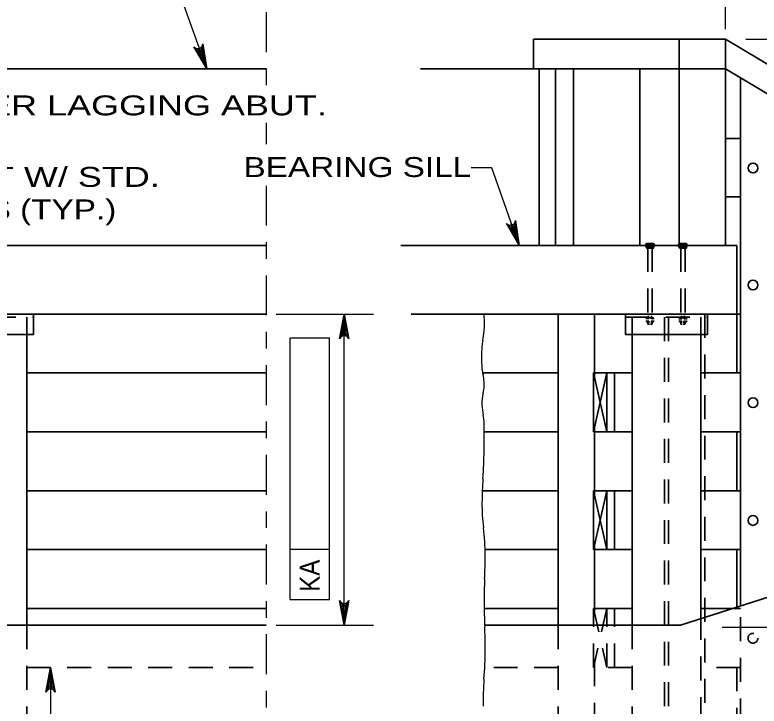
# Model space of a CAD drawing. Extents: x -6.4 to 73.1, y -66 to 0.
# Drawn here: x 46.524 to 51.006, y -62.719 to -58.56 of the extents above; entities that cross this region are included whole.
import ezdxf
from ezdxf.enums import TextEntityAlignment as Align

# ---------------------------------------------------------------- set-up
doc = ezdxf.new("R2010")
doc.units = 0
doc.header["$LTSCALE"] = 0.048
doc.header["$PDMODE"] = 32
doc.header["$PDSIZE"] = 0.024
doc.linetypes.add('DOT_DASHED', pattern=[7.7, 5, -1.2, 0.3, -1.2])
doc.linetypes.add('MEDIUM_DASHED', pattern=[4.5, 3, -1.5])
for name, color, linetype, lineweight in [('3', 7, 'Continuous', 35), ('4', 7, 'Continuous', 25), ('5', 7, 'Continuous', 25), ('8', 7, 'Continuous', 25)]:
    doc.layers.add(name, color=color, linetype=linetype, lineweight=lineweight)

msp = doc.modelspace()

# ---------------------------------------------------------------- hatches: boundary and pattern name
at = {"layer": '4'}
for points in [[(47.65875, -58.77033), (47.62308, -58.78283), (47.6785, -58.88358)], [(49.56125, -59.9465), (49.53158, -59.83175), (49.513, -59.83825)], [(48.48683, -60.478), (48.52625, -60.478), (48.50658, -60.35992)], [(48.48683, -62.1145), (48.52625, -62.1145), (48.50658, -62.23267)], [(46.71958, -62.604), (46.75892, -62.604), (46.73925, -62.48592)]]:
    msp.add_hatch(color=256, dxfattribs=at).paths.add_polyline_path(points)

# ---------------------------------------------------------------- linework, layer by layer
at = {"layer": '3'}
for p, q in [((49.64783, -58.70642), (50.80342, -58.70642)), ((49.64783, -58.70642), (49.64783, -58.88358)), ((50.52408, -58.70642), (50.52408, -58.88358)), ((50.80342, -58.70642), (54.32033, -60.80333)), ((50.80342, -58.70642), (50.80342, -58.88358)), ((42.61283, -58.88358), (48.03658, -58.88358)), ((48.96758, -58.88358), (50.80342, -58.88358)), ((49.68067, -58.88358), (49.68067, -59.9465)), ((49.77892, -58.88358), (49.77892, -59.9465)), ((49.889, -58.88358), (49.889, -59.9465)), ((50.28717, -58.88358), (50.28717, -59.9465)), ((50.52408, -58.88358), (50.52408, -59.9465)), ((50.80342, -58.88358), (54.32033, -60.9805)), ((50.80342, -58.88358), (50.80342, -59.9465)), ((50.89308, -62.1165), (50.89308, -58.93708)), ((50.89308, -59.30242), (50.80342, -59.30242)), ((50.89308, -59.654), (50.80342, -59.654)), ((41.76775, -59.9465), (48.03658, -59.9465)), ((48.84883, -59.9465), (50.87233, -59.9465)), ((50.32783, -59.96242), (50.32783, -59.95025)), ((50.36558, -59.9465), (50.33317, -59.9465)), ((50.33892, -59.95025), (50.33892, -59.96242)), ((50.36025, -59.95025), (50.36025, -59.96242)), ((50.52567, -59.96242), (50.52567, -59.95025)), ((50.56833, -59.96242), (50.52567, -59.96242)), ((50.53067, -59.9465), (50.563, -59.9465)), ((50.536, -59.95025), (50.536, -59.96242)), ((50.55733, -59.95025), (50.55733, -59.96242)), ((50.56833, -59.96242), (50.56833, -59.95025)), ((50.87233, -59.9465), (50.87233, -60.71425)), ((41.76775, -60.35992), (48.03658, -60.35992)), ((46.63633, -60.35992), (46.63633, -60.48292)), ((48.91108, -60.35992), (50.89308, -60.35992)), ((49.7955, -60.35992), (49.7955, -62.23267)), ((50.01558, -60.35992), (50.01558, -60.74467)), ((50.2005, -60.35992), (50.2005, -60.48292)), ((50.69567, -60.35992), (50.69567, -60.48292)), ((50.32742, -60.39133), (50.32742, -60.386)), ((50.32742, -60.40433), (50.32742, -60.39808)), ((50.36517, -60.38225), (50.33275, -60.38225)), ((50.34383, -60.40808), (50.33275, -60.40808)), ((50.34492, -60.375), (50.336, -60.375)), ((50.336, -60.40808), (50.336, -60.42092)), ((50.3385, -60.386), (50.3385, -60.39133)), ((50.3385, -60.39808), (50.3385, -60.40433)), ((50.36225, -60.375), (50.35392, -60.375)), ((50.36517, -60.40808), (50.35433, -60.40808)), ((50.35983, -60.386), (50.35983, -60.39133)), ((50.35983, -60.39808), (50.35983, -60.40433)), ((50.36225, -60.40808), (50.36225, -60.42092)), ((50.37008, -60.39133), (50.37008, -60.386)), ((50.37008, -60.40433), (50.37008, -60.39808)), ((50.526, -60.39192), (50.526, -60.386)), ((50.526, -60.40433), (50.526, -60.398)), ((50.531, -60.38225), (50.56333, -60.38225)), ((50.531, -60.40808), (50.54333, -60.40808)), ((50.53383, -60.375), (50.54333, -60.375)), ((50.53383, -60.40808), (50.53383, -60.42092)), ((50.53633, -60.386), (50.53633, -60.39192)), ((50.53633, -60.398), (50.53633, -60.40433)), ((50.54933, -60.40808), (50.56333, -60.40808)), ((50.5505, -60.375), (50.56008, -60.375)), ((50.55767, -60.386), (50.55767, -60.39192)), ((50.55767, -60.398), (50.55767, -60.40433)), ((50.56008, -60.40808), (50.56008, -60.42092)), ((50.56867, -60.39192), (50.56867, -60.386)), ((50.56867, -60.40433), (50.56867, -60.398)), ((50.3455, -60.42092), (50.336, -60.42092)), ((50.36225, -60.42092), (50.35275, -60.42092)), ((50.53383, -60.42092), (50.54333, -60.42092)), ((50.54933, -60.42092), (50.56008, -60.42092)), ((46.14117, -60.48292), (46.63633, -60.48292)), ((46.59533, -60.48292), (46.59533, -62.23267)), ((50.2005, -60.48292), (50.69567, -60.48292)), ((50.2415, -60.48292), (50.2415, -62.23267)), ((50.65467, -60.48292), (50.65467, -62.1765)), ((46.59533, -60.71425), (48.03658, -60.71425)), ((49.7955, -60.71425), (49.34075, -60.71425)), ((50.00875, -61.06858), (50.00875, -60.71425)), ((50.00875, -60.71425), (50.089, -61.06858)), ((50.089, -60.71425), (50.00875, -61.06858)), ((50.2415, -60.71425), (50.00875, -60.71425)), ((50.089, -61.06858), (50.089, -60.71425)), ((50.13442, -61.06858), (50.13442, -60.71425)), ((50.2415, -60.71425), (50.19825, -60.71425)), ((50.89308, -60.71425), (50.65467, -60.71425)), ((50.01558, -61.03817), (50.01558, -61.45333)), ((46.59533, -61.06858), (48.03658, -61.06858)), ((49.7955, -61.06858), (49.35083, -61.06858)), ((50.2415, -61.06858), (50.00875, -61.06858)), ((54.16433, -61.06375), (50.53233, -62.23267)), ((50.89308, -61.06858), (50.65467, -61.06858)), ((50.87233, -61.06858), (50.87233, -61.42292)), ((46.59533, -61.42292), (48.03658, -61.42292)), ((49.7955, -61.42292), (49.33875, -61.42292)), ((50.00875, -61.77725), (50.00875, -61.42292)), ((50.00875, -61.42292), (50.089, -61.77725)), ((50.2415, -61.42292), (50.00875, -61.42292)), ((50.13442, -61.77725), (50.13442, -61.42292)), ((50.89308, -61.42292), (50.65467, -61.42292)), ((50.01558, -61.74683), (50.01558, -62.162)), ((46.59533, -61.77725), (48.03658, -61.77725)), ((49.7955, -61.77725), (49.356, -61.77725)), ((50.2415, -61.77725), (50.00875, -61.77725)), ((50.89308, -61.77725), (50.65467, -61.77725)), ((50.87233, -61.77725), (50.87233, -62.13158)), ((46.59533, -62.13158), (48.03658, -62.13158)), ((49.7955, -62.13158), (49.35033, -62.13158)), ((50.2415, -62.13158), (50.00875, -62.13158)), ((50.89308, -62.13158), (50.65467, -62.13158)), ((42.0525, -62.23267), (48.03658, -62.23267)), ((49.35308, -62.23267), (50.53233, -62.23267))]:
    msp.add_line(p, q, dxfattribs=at)
at = {"layer": '3', "linetype": 'MEDIUM_DASHED'}
for p, q in [((50.33608, -59.96242), (50.33608, -60.38225)), ((50.36233, -59.96242), (50.36233, -60.38225)), ((50.53392, -59.96242), (50.53392, -60.38225)), ((50.56017, -59.96242), (50.56017, -60.38225)), ((50.67908, -60.35992), (50.67908, -63.54892)), ((50.89308, -63.54892), (50.89308, -62.1165)), ((50.00875, -62.48592), (50.00875, -62.13158)), ((50.00875, -62.13158), (50.089, -62.48592)), ((50.13442, -62.48592), (50.13442, -62.13158)), ((50.65467, -62.1765), (50.65467, -64.00717)), ((46.59533, -62.23267), (46.59533, -64.01633)), ((49.7955, -62.23267), (49.7955, -63.54892)), ((50.2415, -62.23267), (50.2415, -64.01808)), ((50.01558, -62.4555), (50.01558, -62.87067)), ((46.59533, -62.48592), (48.03658, -62.48592)), ((49.7955, -62.48592), (49.35383, -62.48592)), ((50.2415, -62.48592), (50.00875, -62.48592)), ((50.89308, -62.48592), (50.65467, -62.48592)), ((50.87233, -62.48592), (50.87233, -62.84025))]:
    msp.add_line(p, q, dxfattribs=at)
at = {"layer": '3'}
for points in [[(50.32783, -59.96242), (50.3705, -59.96242), (50.3705, -59.95025)], [(50.089, -61.77725), (50.089, -61.42292), (50.00875, -61.77725)]]:
    msp.add_lwpolyline(points, dxfattribs=at)
at = {"layer": '3', "linetype": 'MEDIUM_DASHED'}
msp.add_lwpolyline([(50.089, -62.48592), (50.089, -62.13158), (50.00875, -62.48592)], dxfattribs=at)
at = {"layer": '3'}
for centre in [(50.96877, -59.48111), (50.96877, -60.18474), (50.96877, -60.8934), (50.96877, -61.60206)]:
    msp.add_circle(centre, 0.02953, dxfattribs=at)
at = {"layer": '3', "linetype": 'MEDIUM_DASHED'}
msp.add_circle((50.96877, -62.31072), 0.02953, dxfattribs=at)
at = {"layer": '3'}
for centre, radius, start, end in [((50.33336, -59.95243), 0.00592, 88.17294, 158.71305), ((50.33336, -59.95243), 0.00592, 21.28694, 88.17294), ((50.34954, -59.96347), 0.01696, 51.05, 128.95), ((50.36535, -59.95189), 0.00539, 17.45181, 162.54819), ((50.53082, -59.95189), 0.00539, 17.45181, 162.54819), ((50.54663, -59.96347), 0.01696, 51.05, 128.95), ((50.56281, -59.95243), 0.00592, 91.82706, 158.71306), ((50.56281, -59.95243), 0.00592, 21.28694, 91.82706), ((50.33299, -60.38818), 0.00592, 88.17294, 158.71305), ((50.33299, -60.40216), 0.00592, 201.28694, 271.82706), ((50.33299, -60.38818), 0.00592, 21.28694, 88.17294), ((50.33299, -60.40216), 0.00592, 271.82706, 338.71306), ((50.34917, -60.39922), 0.01696, 51.05, 128.95), ((50.34917, -60.39113), 0.01696, 231.05, 256.0077), ((50.34917, -60.39113), 0.01696, 284.34274, 308.95), ((50.36497, -60.38764), 0.00539, 17.45181, 162.54819), ((50.36497, -60.4027), 0.00539, 197.45181, 342.54819), ((50.5312, -60.38764), 0.00539, 17.45181, 162.54819), ((50.5312, -60.4027), 0.00539, 197.45181, 342.54819), ((50.54701, -60.39922), 0.01696, 51.05, 128.95), ((50.54701, -60.39113), 0.01696, 231.05, 257.49177), ((50.54701, -60.39113), 0.01696, 277.88621, 308.95), ((50.56319, -60.38818), 0.00592, 91.82706, 158.71306), ((50.56319, -60.40216), 0.00592, 201.28694, 268.17294), ((50.56319, -60.38818), 0.00592, 21.28694, 91.82706), ((50.56319, -60.40216), 0.00592, 268.17294, 338.71305)]:
    msp.add_arc(centre, radius, start, end, dxfattribs=at)
at = {"layer": '3', "lineweight": 25}
for centre, radius, start, end in [((48.49638, -60.42412), 0.85604, 0, 4.30041), ((48.04115, -60.29643), 1.31933, 350.22511, 352.77729), ((49.04869, -60.42412), 0.30373, 352.77729, 0), ((50.04974, -60.6168), 0.71552, 174.85038, 180), ((49.73735, -60.58865), 0.40185, 170.22511, 174.85038), ((50.21307, -60.6168), 0.87884, 180, 184.64624), ((49.56984, -60.66908), 0.2335, 184.64624, 194.09577), ((49.09873, -60.78738), 0.25224, 5.00495, 14.09577), ((49.14996, -60.78289), 0.20082, 345.34471, 5.00496), ((49.56975, -60.89267), 0.23309, 165.34471, 183.58075), ((49.83395, -60.87614), 0.4978, 183.58075, 190.71943), ((49.04664, -61.02518), 0.30349, 1.57285, 10.71943), ((47.11271, -61.07828), 2.23815, 0, 1.57285), ((42.6605, -61.07828), 6.69035, 359.0903, 0), ((46.35757, -61.13699), 2.99281, 355.92772, 359.0903), ((51.63092, -61.51242), 2.29388, 175.92772, 179.54026), ((50.48062, -61.50319), 1.14355, 179.54026, 187.19626), ((48.03942, -61.81143), 1.31704, 0.06302, 7.19626), ((46.38007, -61.81325), 2.97639, 357.26093, 0.06302), ((52.03522, -62.0838), 2.68522, 177.26093, 180.21106), ((53.06831, -62.08), 3.71833, 180.21106, 182.50023), ((46.27447, -62.37665), 3.08199, 359.98578, 2.50023), ((47.0813, -62.37685), 2.27516, 355.43722, 359.98579), ((51.16176, -62.70249), 1.81827, 175.43722, 180.5256)]:
    msp.add_arc(centre, radius, start, end, dxfattribs=at)
at = {"layer": '3'}
for p in [(50.335, -59.94667), (50.33558, -59.94667), (50.33625, -59.94667), (50.3365, -59.94725), (50.33683, -59.94667), (50.33708, -59.94725), (50.33742, -59.94667), (50.33742, -59.94783), (50.33767, -59.94725), (50.338, -59.94667), (50.338, -59.94783), (50.33825, -59.94725), (50.33833, -59.94842), (50.33858, -59.94667), (50.33858, -59.94783), (50.33858, -59.949), (50.33883, -59.94725), (50.33883, -59.94842), (50.33883, -59.94958), (50.33917, -59.94667), (50.33917, -59.94783), (50.33917, -59.949), (50.3395, -59.94725), (50.3395, -59.94842), (50.3395, -59.94958), (50.33975, -59.94667), (50.33975, -59.94783), (50.33975, -59.949), (50.34008, -59.94725), (50.34008, -59.94842), (50.34033, -59.94667), (50.34033, -59.94783), (50.34033, -59.949), (50.34067, -59.94725), (50.34067, -59.94842), (50.34092, -59.94667), (50.34092, -59.94783), (50.34125, -59.94725), (50.34125, -59.94842), (50.3415, -59.94667), (50.3415, -59.94783), (50.34183, -59.94725), (50.34208, -59.94667), (50.34208, -59.94783), (50.34242, -59.94725), (50.34267, -59.94667), (50.34267, -59.94783), (50.343, -59.94725), (50.34333, -59.94667), (50.34358, -59.94725), (50.34392, -59.94667), (50.34417, -59.94725), (50.3445, -59.94667), (50.34508, -59.94667), (50.34567, -59.94667), (50.34625, -59.94667), (50.34683, -59.94667), (50.35217, -59.94667), (50.35275, -59.94667), (50.35333, -59.94667), (50.35392, -59.94667), (50.3545, -59.94667), (50.35483, -59.94725), (50.35508, -59.94667), (50.35542, -59.94725), (50.35575, -59.94667), (50.356, -59.94725), (50.35625, -59.94667), (50.35625, -59.94783), (50.35658, -59.94725), (50.35692, -59.94667), (50.35692, -59.94783), (50.35717, -59.94725), (50.3575, -59.94667), (50.3575, -59.94783), (50.35775, -59.94725), (50.35775, -59.94842), (50.35808, -59.94667), (50.35808, -59.94783), (50.35833, -59.94725), (50.35833, -59.94842), (50.35867, -59.94667), (50.35867, -59.94783), (50.35867, -59.949), (50.35892, -59.94725), (50.35892, -59.94842), (50.35925, -59.94667), (50.35925, -59.94783), (50.35925, -59.949), (50.3595, -59.94725), (50.3595, -59.94842), (50.3595, -59.94958), (50.35983, -59.94667), (50.35983, -59.94783), (50.35983, -59.949), (50.36008, -59.94725), (50.36008, -59.94842), (50.36008, -59.94958), (50.36025, -59.94725), (50.36025, -59.94842), (50.36025, -59.94958), (50.3605, -59.94667), (50.3605, -59.94783), (50.3605, -59.949), (50.36083, -59.94725), (50.36083, -59.94842), (50.36108, -59.94667), (50.36108, -59.94783), (50.36142, -59.94725), (50.36175, -59.94667), (50.36175, -59.94783), (50.362, -59.94725), (50.36225, -59.94667), (50.36258, -59.94725), (50.36292, -59.94667), (50.3635, -59.94667), (50.36408, -59.94667), (50.53208, -59.94667), (50.53267, -59.94667), (50.53333, -59.94667), (50.53358, -59.94725), (50.53392, -59.94667), (50.53417, -59.94725), (50.5345, -59.94667), (50.5345, -59.94783), (50.53475, -59.94725), (50.53508, -59.94667), (50.53508, -59.94783), (50.53533, -59.94725), (50.53542, -59.94842), (50.53567, -59.94667), (50.53567, -59.94783), (50.53567, -59.949), (50.53592, -59.94725), (50.53592, -59.94842), (50.53592, -59.94958), (50.53608, -59.94725), (50.53608, -59.94842), (50.53608, -59.94958), (50.53633, -59.94667), (50.53633, -59.94783), (50.53633, -59.949), (50.53667, -59.94725), (50.53667, -59.94842), (50.53667, -59.94958), (50.53692, -59.94667), (50.53692, -59.94783), (50.53692, -59.949), (50.53725, -59.94725), (50.53725, -59.94842), (50.5375, -59.94667), (50.5375, -59.94783), (50.5375, -59.949), (50.53783, -59.94725), (50.53783, -59.94842), (50.53808, -59.94667), (50.53808, -59.94783), (50.53842, -59.94725), (50.53842, -59.94842), (50.53867, -59.94667), (50.53867, -59.94783), (50.539, -59.94725), (50.53933, -59.94667), (50.53933, -59.94783), (50.53958, -59.94725), (50.53992, -59.94667), (50.53992, -59.94783), (50.54017, -59.94725), (50.5405, -59.94667), (50.54075, -59.94725), (50.54108, -59.94667), (50.54142, -59.94725), (50.54167, -59.94667), (50.54225, -59.94667), (50.54283, -59.94667), (50.54342, -59.94667), (50.544, -59.94667), (50.54933, -59.94667), (50.54992, -59.94667), (50.5505, -59.94667), (50.55108, -59.94667), (50.55175, -59.94667), (50.552, -59.94725), (50.55225, -59.94667), (50.55258, -59.94725), (50.55292, -59.94667), (50.55317, -59.94725), (50.5535, -59.94667), (50.5535, -59.94783), (50.55375, -59.94725), (50.55408, -59.94667), (50.55408, -59.94783), (50.55433, -59.94725), (50.55467, -59.94667), (50.55467, -59.94783), (50.55492, -59.94725), (50.55492, -59.94842), (50.55525, -59.94667), (50.55525, -59.94783), (50.55558, -59.94725), (50.55558, -59.94842), (50.55583, -59.94667), (50.55583, -59.94783), (50.55583, -59.949), (50.55608, -59.94725), (50.55608, -59.94842), (50.55642, -59.94667), (50.55642, -59.94783), (50.55642, -59.949), (50.55675, -59.94725), (50.55675, -59.94842), (50.55675, -59.94958), (50.557, -59.94667), (50.557, -59.94783), (50.557, -59.949), (50.55733, -59.94725), (50.55733, -59.94842), (50.55733, -59.94958), (50.55758, -59.94667), (50.55758, -59.94783), (50.55758, -59.949), (50.55792, -59.94725), (50.55792, -59.94842), (50.55817, -59.94667), (50.55817, -59.94783), (50.5585, -59.94725), (50.55883, -59.94667), (50.55883, -59.94783), (50.55908, -59.94725), (50.55933, -59.94667), (50.55967, -59.94725), (50.56, -59.94667), (50.56058, -59.94667), (50.56117, -59.94667)]:
    msp.add_point(p, dxfattribs=at)
at = {"layer": '4'}
for p, q in [((50.80342, -58.64483), (50.80342, -56.891)), ((47.67925, -58.88358), (47.31142, -57.85708)), ((50.92517, -58.70642), (51.165, -58.70642)), ((48.09808, -60.35992), (48.68375, -60.35992)), ((48.50658, -62.23267), (48.50658, -60.35992)), ((48.18167, -62.07767), (48.18167, -60.50283)), ((48.18167, -60.50283), (48.41783, -60.50283)), ((48.41783, -62.07767), (48.41783, -60.50283)), ((48.18167, -61.77517), (48.41783, -61.77517)), ((48.18167, -62.07767), (48.41783, -62.07767)), ((48.09808, -62.23267), (48.68375, -62.23267)), ((54.60633, -62.247), (50.78325, -62.247)), ((46.73925, -62.48592), (46.73925, -63.54008))]:
    msp.add_line(p, q, dxfattribs=at)
at = {"layer": '4', "linetype": 'DOT_DASHED'}
for p, q in [((48.03658, -58.003), (48.03658, -58.99125)), ((48.03658, -59.20933), (48.03658, -59.33717)), ((48.03658, -59.58725), (48.03658, -63.623))]:
    msp.add_line(p, q, dxfattribs=at)
at = {"layer": '4', "lineweight": 35}
msp.add_line((50.89308, -59.64058), (50.89308, -61.52375), dxfattribs=at)
at = {"layer": '4'}
for points in [[(47.67925, -58.88358), (47.60258, -58.75267), (47.614, -58.76075), (47.62542, -58.763), (47.63542, -58.76117), (47.64425, -58.75625), (47.65167, -58.74725), (47.65525, -58.73375), (47.67925, -58.88358), (47.65167, -58.74725), (47.64425, -58.75625), (47.67925, -58.88358), (47.63542, -58.76117), (47.62542, -58.763), (47.67925, -58.88358), (47.614, -58.76075)], [(49.56125, -59.9465), (49.39642, -59.4805), (49.27133, -59.4805)], [(49.56125, -59.9465), (49.48575, -59.81492), (49.497, -59.82317), (49.50842, -59.82542), (49.51842, -59.82375), (49.52733, -59.81883), (49.53475, -59.80992), (49.5385, -59.7965), (49.56125, -59.9465), (49.53475, -59.80992), (49.52733, -59.81883), (49.56125, -59.9465), (49.51842, -59.82375), (49.50842, -59.82542), (49.56125, -59.9465), (49.497, -59.82317)], [(48.50658, -60.35992), (48.53458, -60.50908), (48.52658, -60.49758), (48.51658, -60.49167), (48.50658, -60.48992), (48.49658, -60.49167), (48.48658, -60.49758), (48.47858, -60.50908), (48.50658, -60.35992), (48.48658, -60.49758), (48.49658, -60.49167), (48.50658, -60.35992), (48.50658, -60.48992), (48.51658, -60.49167), (48.50658, -60.35992), (48.52658, -60.49758)], [(48.50658, -62.23267), (48.47858, -62.0835), (48.48658, -62.095), (48.49658, -62.10092), (48.50658, -62.10267), (48.51658, -62.10092), (48.52658, -62.095), (48.53458, -62.0835), (48.50658, -62.23267), (48.52658, -62.095), (48.51658, -62.10092), (48.50658, -62.23267), (48.50658, -62.10267), (48.49658, -62.10092), (48.50658, -62.23267), (48.48658, -62.095)], [(46.73925, -62.48592), (46.76725, -62.63508), (46.75925, -62.62358), (46.74925, -62.61767), (46.73925, -62.61592), (46.72925, -62.61767), (46.71925, -62.62358), (46.71125, -62.63508), (46.73925, -62.48592), (46.71925, -62.62358), (46.72925, -62.61767), (46.73925, -62.48592), (46.73925, -62.61592), (46.74925, -62.61767), (46.73925, -62.48592), (46.75925, -62.62358)]]:
    msp.add_lwpolyline(points, dxfattribs=at)
for points in [[(47.65875, -58.77033), (47.62308, -58.78283), (47.6785, -58.88358)], [(49.56125, -59.9465), (49.53158, -59.83175), (49.513, -59.83825)], [(48.48683, -60.478), (48.52625, -60.478), (48.50658, -60.35992)], [(48.48683, -62.1145), (48.52625, -62.1145), (48.50658, -62.23267)], [(46.71958, -62.604), (46.75892, -62.604), (46.73925, -62.48592)]]:
    msp.add_lwpolyline(points, close=True, dxfattribs=at)
at = {"layer": '8', "linetype": 'MEDIUM_DASHED', "lineweight": 35}
for p, q in [((46.14117, -60.37958), (46.63633, -60.37958)), ((46.59533, -60.37958), (46.59533, -60.48292)), ((50.2005, -60.37958), (50.69567, -60.37958)), ((50.2415, -60.37958), (50.2415, -60.48292)), ((50.43633, -60.37958), (50.43633, -64.01408)), ((50.46, -60.37958), (50.46, -64.02892)), ((50.65467, -60.37958), (50.65467, -60.48292))]:
    msp.add_line(p, q, dxfattribs=at)

# ---------------------------------------------------------------- texts
at = {"layer": '4'}
for s, width, p in [('BEARING SILL', 1.25, (47.90075, -59.53533)), ('12.7 (1/2")  BOLT W/ STD.', 1.35, (44.828, -59.5945)), ('NUT & WASHERS (TYP.)', 1.25, (44.828, -59.79033))]:
    msp.add_text(s, height=0.12, dxfattribs=dict(at, width=width)).set_placement(p)
at = {"layer": '4', "width": 0.9}
msp.add_text('KA', height=0.12, rotation=90, dxfattribs=at).set_placement((48.35983, -61.9345), align=Align.CENTER)
at = {"layer": '5', "width": 1.35}
msp.add_text('76x305 (3"x12") TIMBER LAGGING ABUT.', height=0.12, dxfattribs=at).set_placement((44.24033, -59.16425))

doc.saveas('drawing.dxf')
